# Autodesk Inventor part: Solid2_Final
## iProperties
Created: 2009-02
Part Number: Solid2_Final
Document SubType Name: Modeling
Designer: Autodesk
Density: 1 g/cm^3
Author: Autodesk
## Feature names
1. TaggingFeature1
